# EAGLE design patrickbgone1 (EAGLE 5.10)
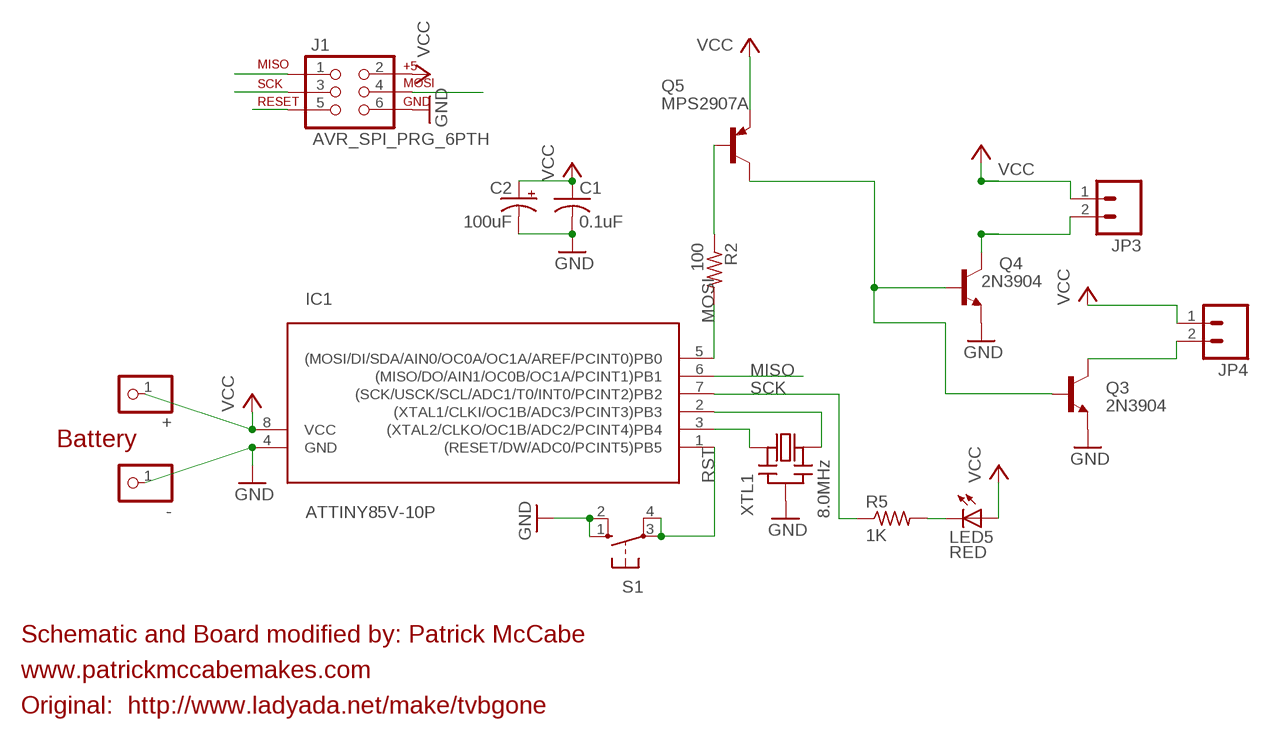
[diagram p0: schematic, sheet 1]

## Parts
+  PINHD-1X1  [1X01]
-  PINHD-1X1  [1X01]
C1  0.1uF  C-US025-025X050  [C025-025X050]
C2  100uF  CPOL-USE2.5-5  [E2,5-5]
IC1  ATTINY85V-10P  [DIL08]
J1  AVR_SPI_PRG_6PTH  [2X3]
JP3  M02PTH  [1X02]
JP4  M02PTH  [1X02]
LED5  RED  LED3MM  [LED3MM]
Q3  2N3904  2N3904EZ  [TO92-EZ]
Q4  2N3904  2N3904EZ  [TO92-EZ]
Q5  MPS2907A  [TO92-CBE]
R2  100  R-US_0207/2V  [0207/2V]
R5  1K  R-US_0207/2V  [0207/2V]
S1  10-XX  [B3F-10XX]
XTL1  8.0MHz  CERMOSCILL  [CERM_OSC]

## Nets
GND: -.1 C1.2 C2.- IC1.4(GND) J1.6 Q3.3(E) Q4.3(E) S1.1(S) S1.2(S1) XTL1.P$2(GND)
MISO: IC1.6((MISO/DO/AIN1/OC0B/OC1A/PCINT1)PB1) J1.1
MOSI: IC1.5((MOSI/DI/SDA/AIN0/OC0A/OC1A/AREF/PCINT0)PB0) J1.4 R2.2
N$1: IC1.3((XTAL2/CLKO/OC1B/ADC2/PCINT4)PB4) XTL1.P$1(IN)
N$2: IC1.2((XTAL1/CLKI/OC1B/ADC3/PCINT3)PB3) XTL1.P$3(OUT)
N$3: LED5.K(C) R5.2
N$4: Q3.2(B) Q4.2(B) Q5.C
N$6: Q5.B R2.1
N$7: JP3.2 Q4.1(C)
N$9: JP4.2 Q3.1(C)
RST: IC1.1((RESET/DW/ADC0/PCINT5)PB5) J1.5 S1.3(P) S1.4(P1)
SCK: IC1.7((SCK/USCK/SCL/ADC1/T0/INT0/PCINT2)PB2) J1.3 R5.1
VCC: +.1 C1.1 C2.+ IC1.8(VCC) J1.2 JP3.1 JP4.1 LED5.A Q5.E

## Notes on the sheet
- Battery
- Schematic and Board modified by: Patrick McCabe
- www.patrickmccabemakes.com
- Original: | http://www.ladyada.net/make/tvbgone

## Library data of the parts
+ - = ybox2:PINHD-1X1: PIN HEADER
C1 = rcl-ez:C-US: CAPACITOR, American symbol
C2 = rcl-ez:CPOL-US: POLARIZED CAPACITOR, American symbol
IC1 = avr:ATTINY85: MICROCONTROLLER 8 Kbytes FLASH 512 bytes EEPROM 512 bytes RAM 4-channel 10 bit ADC USI
J1 = SparkFun:AVR_SPI_PRG_6: AVR ISP 6 Pin This is the reduced ISP connector for AVR programming. Common on Arduino. This footprint will take up less PCB space and can be used with a 10-pin to 6-pin adapter such as SKU: BOB-08508
JP3 JP4 = SparkFun:M02: Header 2
LED5 = minimidi:LED: LED
Q3 Q4 = transistor-npn:2N3904: NPN Transistor
Q5 = transistor-pnp:MPS2907*: PNP Transistror
R2 R5 = rcl-ez:R-US_: RESISTOR, American symbol
S1 = switch-omron:10-XX: OMRON SWITCH
XTL1 = digg:CERMOSCILL

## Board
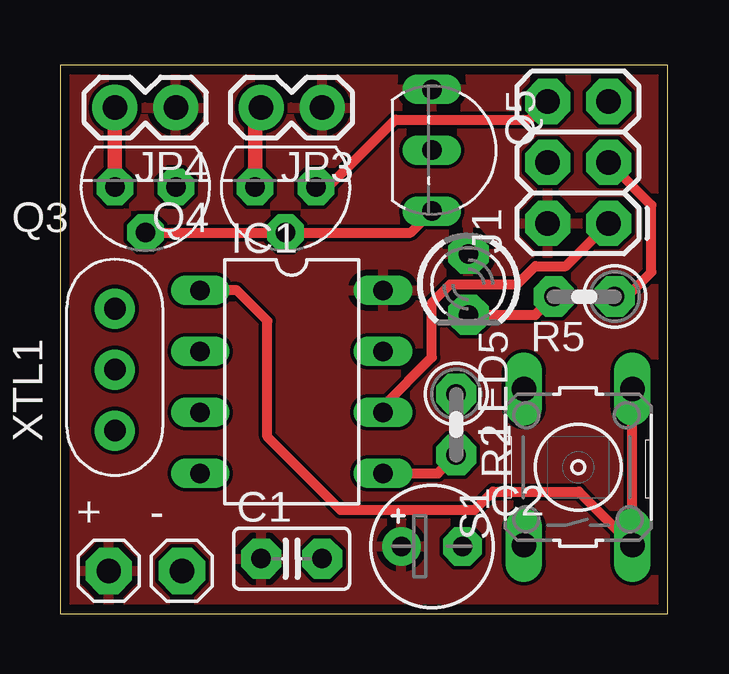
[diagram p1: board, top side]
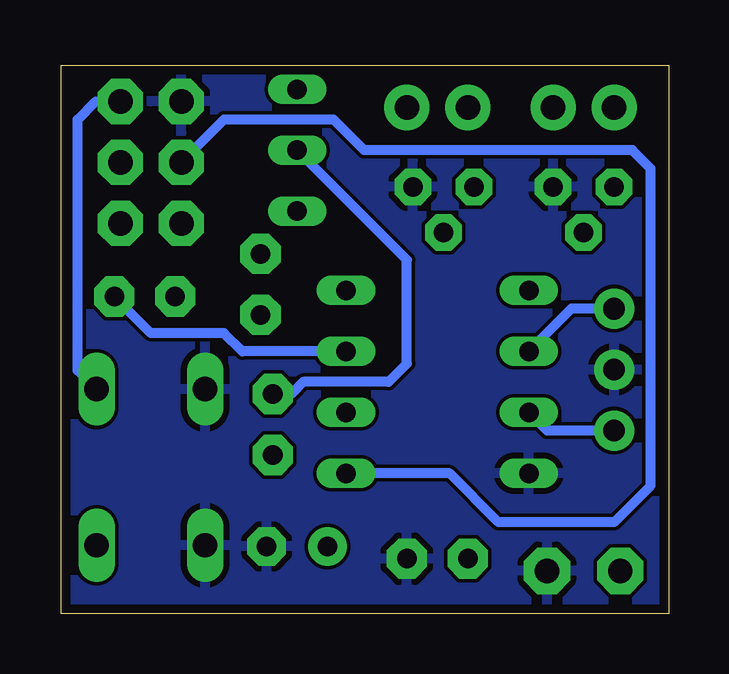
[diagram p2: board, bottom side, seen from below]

Size 25.32 x 22.85 mm. Coordinates in mm from the lower left corner, seen from the top.
Outline: 0,0 25.32,0 25.32,22.85 0,22.85 0,0
Copper layers (1*16): Top 0.0356mm / dielectric 1.5011mm / Bottom 0.0356mm
Design rules "Dorkbot": minimum track width 6mil, minimum drill 13mil, track to track 6mil, track to pad 6mil, pad to pad 6mil, via to via 6mil, smd to smd 6mil, copper to edge 15mil, drill to drill 6mil, minimum pad ring 7mil, minimum via ring 7mil, stop-mask expansion 4mil, vias tented up to drill 0mil, thermal gap 10mil

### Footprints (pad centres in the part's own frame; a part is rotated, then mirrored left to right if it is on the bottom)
1X01 = drill 1.016 pad 1.93 octagon: 1 0,0
C025-025X050 = drill 0.813 pad 1.676 octagon: 1 -1.27,0; 2 1.27,0
E2,5-5 = drill 0.813 pad 1.6 round: + -1.27,0 | drill 0.813 pad 1.6 octagon: - 1.27,0
DIL08 = drill 0.813 long: 1 -3.81,-3.81; 2 -1.27,-3.81; 3 1.27,-3.81; 4 3.81,-3.81; 5 3.81,3.81; 6 1.27,3.81; 7 -1.27,3.81; 8 -3.81,3.81
2X3 = drill 1.016 pad 1.88 octagon: 1 0,0; 2 0,2.54; 3 2.54,0; 4 2.54,2.54; 5 5.08,0; 6 5.08,2.54
1X02 = drill 1.016 pad 1.88 round: 1 0,0; 2 2.54,0
LED3MM = drill 0.813 pad 1.676 octagon: A -1.27,0; K 1.27,0
TO92-EZ = drill 0.813 pad 1.524 octagon: 1 1.27,0; 2 0,1.905; 3 -1.27,0
TO92-CBE = drill 0.813 long: B 0,0; C 2.54,0; E -2.54,0
0207/2V = drill 0.813 pad 1.676 octagon: 1 -1.27,0; 2 1.27,0
B3F-10XX = drill 1.016 long: 1 -3.251,2.261; 2 3.251,2.261; 3 -3.251,-2.261; 4 3.251,-2.261
CERM_OSC = drill 0.9 pad 1.676 round: P$1 -2.54,0; P$2 0,0; P$3 2.54,0

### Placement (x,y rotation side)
+  2.03,1.78 0 top
-  5.08,1.78 0 top
C1  9.65,2.29 0 top
C2  15.49,2.79 0 top
IC1  9.65,9.65 270 top
J1  22.86,16.26 90 top
JP3  10.92,21.08 180 top
JP4  4.83,21.08 180 top
LED5  17.02,13.72 270 top
Q3  3.56,17.78 180 top
Q4  9.4,17.78 180 top
Q5  15.49,19.3 270 top
R2  16.51,7.87 270 top
R5  21.84,13.21 180 top
S1  21.59,6.1 90 top
XTL1  2.29,10.16 90 top

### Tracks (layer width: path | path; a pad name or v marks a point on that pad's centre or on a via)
GND
  Top 0.406: Q4.3 11.18,17.78 13.97,20.57 19.56,20.57 J1.6
  pour Bottom: 0,23.11 25.4,23.11 25.4,0 0,0
MISO
  Top 0.406: IC1.6 13.46,8.64 15.49,10.67 15.49,12.95 16.26,13.72 19.05,13.72 19.81,14.48 21.08,14.48 J1.1
MOSI
  Top 0.406: IC1.5 15.75,5.84 R2.2
  Bottom 0.406: IC1.5 9.14,5.84 7.11,3.81 2.29,3.81 0.76,5.33 0.76,18.54 1.52,19.3 12.7,19.3 13.97,20.57 18.54,20.57 J1.4
N$1
  Bottom 0.406: XTL1.P$1 5.08,7.62 IC1.3
N$2
  Bottom 0.406: XTL1.P$3 4.06,12.7 IC1.2
N$3
  Top 0.406: LED5.K 19.81,12.45 R5.2
N$4
  Top 0.406: Q3.2 Q4.2 14.61,15.88 Q5.C
N$6
  Bottom 0.406: R2.1 15.75,9.14 15.24,9.65 11.68,9.65 10.92,10.41 10.92,14.73 Q5.B
N$7
  Top 0.61: Q4.1 8.13,20.83 JP3.2
N$9
  Top 0.61: Q3.1 JP4.2
RST
  Top 0.406: S1.4 S1.3 21.61,5.08 18.03,5.08 17.27,4.32 11.68,4.32 8.64,7.37 8.64,12.19 7.37,13.46 IC1.1
  Bottom 0.406: J1.5 23.88,21.34 24.64,20.57 24.64,10.13 S1.4
SCK
  Top 0.406: R5.1 23.62,13.21 24.64,14.22 24.64,17.02 J1.3
  Bottom 0.406: IC1.7 17.78,10.92 18.54,11.68 21.59,11.68 R5.1
VCC
  pour Top: 0,23.11 25.4,23.11 25.4,0 0,0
